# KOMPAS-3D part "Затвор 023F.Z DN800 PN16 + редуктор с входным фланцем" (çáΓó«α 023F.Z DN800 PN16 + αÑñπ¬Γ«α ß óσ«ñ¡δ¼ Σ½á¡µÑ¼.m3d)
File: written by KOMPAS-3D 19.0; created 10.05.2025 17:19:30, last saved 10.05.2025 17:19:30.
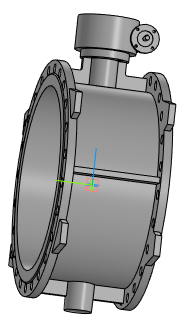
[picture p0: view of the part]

Document properties: Полное имя файла: Затвор 023F.Z DN800 PN16 + редуктор с входным фланцем.a3d

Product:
- Part/product: Затвор 023F.Z DN800 PN16 + редуктор с входным фланцем
    Масса: 783.323

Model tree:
1. Операция без истории:1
